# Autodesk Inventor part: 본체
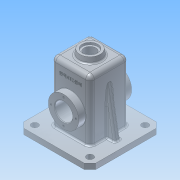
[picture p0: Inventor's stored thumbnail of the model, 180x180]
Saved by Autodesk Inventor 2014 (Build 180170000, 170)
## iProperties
Created: 2016-02
Part Number: 본체
Material: 알루미늄 6061
Document SubType Name: Modeling
Designer: net
Density: 2.71 g/cm^3
Appearance: 알루미늄 - 평지
Mass: 933.449 g
Surface Area: 1043.48 cm^2
Volume: 344.446 cm^3
Author: net
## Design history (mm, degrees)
sketch "스케치1"
  geometry: C1 r 27.5 at (0, 0); 1 further point
  constraints: 1 centre point, 1 coincident
  dimensions: "d0" = 55 diameter of C1
extrude "돌출1" new body sketch "스케치1" stored distance "d1" = 96; taper "d2" = 0 deg
sketch "스케치2"
  geometry: L1 (-35, 65)-(35, 65); L2 (35, 65)-(35, -55); L3 (35, -55)-(-35, -55); L4 (-35, -55)-(-35, 65); 2 further points
  constraints: 8 end point, 2 parallel, 1 horizontal, 1 midpoint, 1 perpendicular, 1 vertical alignment
  dimensions: "d3" = 70 distance of L1.start L1.end; "d4" = 120 distance of L1.end L2.end; "d5" = 55 distance from line of point (0, 0) L3
extrude "돌출2" join sketch "스케치2" stored distance "d6" = 70; taper "d7" = 0 deg
sketch "스케치3"
  geometry: L1 (-30, 30)-(100, 30); L2 (100, 30)-(100, -100); L3 (100, -100)-(-30, -100); L4 (-30, -100)-(-30, 30); 3 further points
  constraints: 8 end point, 2 midpoint, 2 parallel, 1 horizontal, 1 horizontal alignment, 1 perpendicular, 1 vertical alignment
  dimensions: "d8" = 130 distance of L1.start L1.end; "d9" = 130 distance of L1.end L2.end
extrude "돌출3" join sketch "스케치3" distance "d10" = 10; taper "d11" = 0 deg
sketch "스케치5"
  geometry: L1 (-35, 65)-(35, 65) reference; L2 (65, -55)-(-65, -55) reference; L3 (-35, -45)-(-35, 65) reference; L4 (35, 65)-(35, -45) reference; L5 (-30, 60)-(30, 60); L6 (30, 60)-(30, -55); L7 (-30, -55)-(-30, 60); 1 further point
  constraints: 6 end point, 3 parallel, 2 point on line
  dimensions: "d12" = 5 distance between parallel lines of L4 L6; "d13" = 5 distance between parallel lines of L1 L5; "d14" = 5 distance between parallel lines of L3 L7
extrude "돌출4" cut sketch "스케치5" stored distance "d15" = 60; taper "d16" = 0 deg
sketch "스케치6"
  geometry: L1 (-30, 60)-(-30, -55) reference; L2 (0, 0)-(-30, 0); L3 (-30, 27.5)-(-23, 20.5); L4 (-23, 20.5)-(-23, 0); L5 (-35, 65)-(-35, -45) reference
  constraints: 6 end point, 3 point on line, 2 perpendicular
  dimensions: "d17" = 135 deg angle of L3 L4; "d18" = 12 distance between parallel lines of L5 L4; "d19" = 55 diameter of L3.start L2
revolve "회전1" sketch "스케치6" stored, may be unused: angle "d20" = 90 deg
sketch "스케치7"
  geometry: C1 r 20.5 at (0, 0) reference; C2 r 16 at (0, 0)
  constraints: 1 centre point, 1 coincident
  dimensions: "d21" = 32 diameter of C2
extrude "돌출5" cut sketch "스케치7" stored distance "d22" = 60; taper "d23" = 0 deg
sketch "스케치8" dims "d24" = 45
  geometry: C1 r 16 at (0, 0) reference; C2 r 27.5 at (0, 0) reference; 2 further points
  constraints: 2 vertical alignment, 1 coincident, 2 other
hole "구멍1" sketch "스케치8" at (0, 22.5) diameter "d25" = 3.242; stored, may be unused: countersink angle "d29" = 90 deg, drill point angle "d31" = 118 deg; dims "d26" = 8, "d27" = 4, "d28" = 2, "d30" = 10
sketch "스케치9" dims "d35" = 45
  geometry: C1 r 16 at (0, 0) reference; C2 r 27.5 at (0, 0) reference; 2 further points
  constraints: 2 vertical alignment, 1 coincident, 2 other
hole "구멍2" sketch "스케치9" at (0, -22.5) diameter "d36" = 3.242; stored, may be unused: countersink angle "d40" = 90 deg, drill point angle "d42" = 118 deg; dims "d37" = 8, "d38" = 4, "d39" = 2, "d41" = 10
chamfer "모따기1" distance "d46" = 10; stored, may be unused: second distance "d47" = 2, angle "d48" = 45 deg
sketch "스케치10"
  geometry: C1 r 20 at (35, -35); 1 further point
  constraints: 1 centre point, 1 coincident
  dimensions: "d49" = 40 diameter of C1
extrude "돌출6" join sketch "스케치10" distance "d50" = 10; taper "d51" = -10 deg
sketch "스케치15"
  geometry: L1 (-90, -100)-(20, -100) reference; L2 (30, -90)-(30, 20) reference; L3 (20, 30)-(-90, 30) reference; C1 r 6 at (-85, 15); C2 r 6 at (15, 15); C3 r 6 at (-85, -85); C4 r 6 at (15, -85); 1 further point
  constraints: 4 centre point, 3 equal radius, 2 horizontal alignment, 2 vertical alignment
  dimensions: "d58" = 12 diameter of C1; "d60" = 15 distance from line of C2.centre L2; "d61" = 100 distance of C1.centre C2.centre; "d62" = 15 distance from line of C2.centre L3; "d63" = 15 distance from line of C4.centre L1
extrude "돌출9" cut sketch "스케치15" stored distance "d64" = 4; taper "d65" = 0 deg
sketch "스케치16"
  geometry: L1 (-55, -45)-(55, -45) reference; L2 (35, 65)-(35, -45) reference; L3 (50, -45)-(35, 40.069); L4 (65, -45)-(65, -55) reference; 1 further point
  constraints: 2 end point, 2 point on line
  dimensions: "d66" = 10 deg angle of L4 L3; "d67" = 15 distance from line of L4 L3.start
extrude "돌출10" join sketch "스케치16" stored distance "d68" = 10; taper "d69" = 0 deg
sketch "스케치18"
  geometry: C1 r 18.237 at (0, 0) reference; C2 r 10.5 at (0, 0)
  constraints: 1 centre point, 1 coincident
  dimensions: "d70" = 21 diameter of C2
extrude "돌출11" cut sketch "스케치18" stored distance "d71" = 10; taper "d72" = 0 deg
sketch "스케치19"
  geometry: C1 r 10.5 at (0, 0) reference; C2 r 18.237 at (0, 0) reference; C3 r 14 at (0, 0)
  constraints: 1 centre point, 1 coincident
  dimensions: "d73" = 28 diameter of C3
extrude "돌출12" cut sketch "스케치19" distance "d74" = 4; taper "d75" = 0 deg
sketch "스케치20"
  geometry: L1 (35, -45)-(35, 65) reference; L2 (-18.237, 75)-(18.237, 75) reference; 1 further point
  constraints: 1 other
  dimensions: "d76" = 35 distance from line of point (0, 45) L1; "d77" = 30 distance from line of point (0, 45) L2
feature "엠보싱1" sketch "스케치20" dims "d0" = 55, "d10" = 10, "d11" = 0, "d78" = 0.5, "d79" = 0
fillet "모깎기1" dims "d80" = 3
fillet "모깎기2" dims "d81" = 3
fillet "모깎기3" dims "d82" = 3
fillet "모깎기4" dims "d83" = 8
fillet "모깎기5" dims "d84" = 8
chamfer "모따기2" distance "d87" = 1; stored, may be unused: second distance "d88" = 2, angle "d89" = 45 deg
fillet "모깎기8" dims "d90" = 0.5
fillet "모깎기9" dims "d91" = 0.5
sketch "스케치21"
  geometry: C1 r 20.5 at (0, 0) reference; C2 r 16 at (0, 0)
  constraints: 1 centre point, 1 coincident
  dimensions: "d92" = 32 diameter of C2
extrude "돌출13" cut sketch "스케치21" stored distance "d93" = 4; taper "d94" = 0 deg
fillet "모깎기10" dims "d95" = 0.5
fillet "모깎기11" dims "d96" = 0.5
fillet "모깎기13" dims "d98" = 3
fillet "모깎기14" dims "d99" = 3
fillet "모깎기15" dims "d100" = 3
fillet "모깎기16" dims "d101" = 3
node "솔리드1"
pattern_circular "원형 패턴1" dims angle "d33" = 360 deg
pattern_circular "원형 패턴2" dims angle "d44" = 360 deg
mirror "대칭1"
mirror "대칭2"
